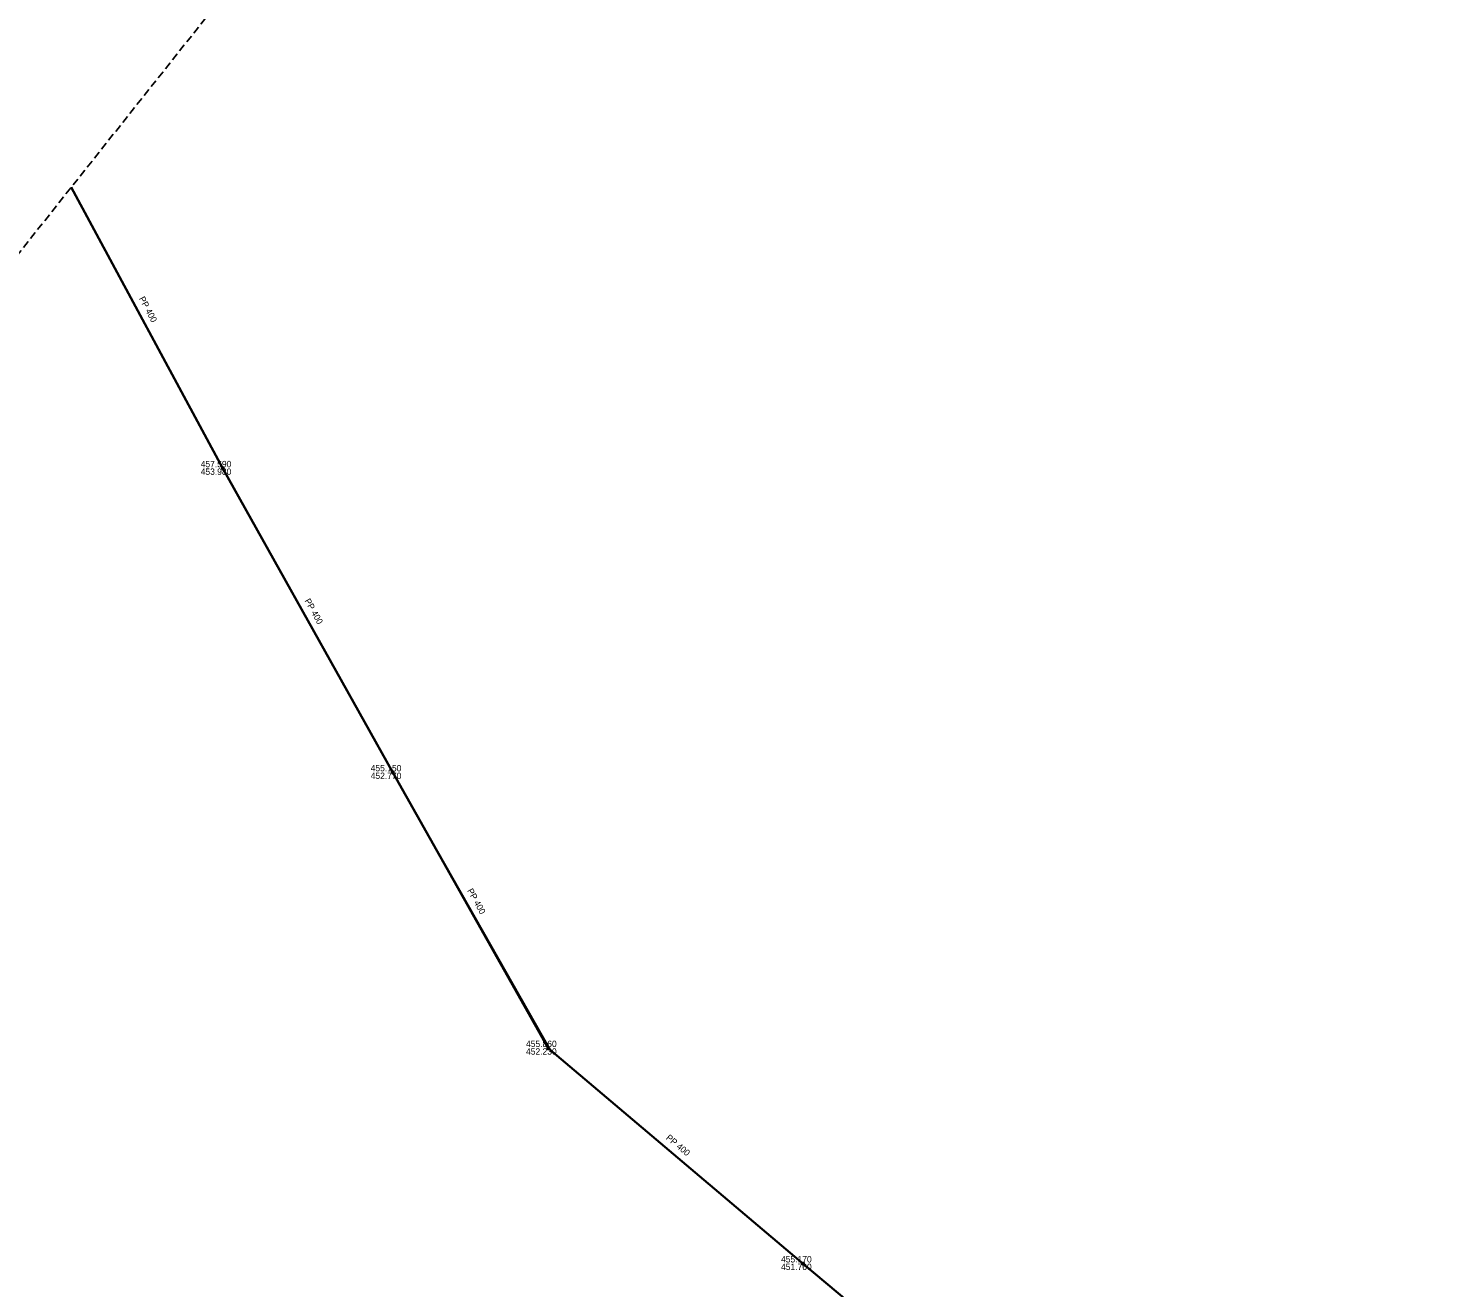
# Model space of a CAD drawing. Extents: x -873619 to -867639, y -1015082 to -1012326.
# Drawn here: x -873315.2 to -873071.1, y -1013648.8 to -1013430.2 of the extents above; entities that cross this region are included whole.
import ezdxf

# ---------------------------------------------------------------- set-up
doc = ezdxf.new("R2010")
doc.units = 0
doc.header["$LTSCALE"] = 0.44
doc.linetypes.add('MEDIUM_DASHED', pattern=[4.5, 3, -1.5])
for name, color, linetype, lineweight in [('1', 7, 'Continuous', 13), ('21', 7, 'Continuous', 35), ('3', 7, 'Continuous', 25), ('32', 7, 'Continuous', 13), ('62', 7, 'MEDIUM_DASHED', 25)]:
    doc.layers.add(name, color=color, linetype=linetype, lineweight=lineweight)

msp = doc.modelspace()

# ---------------------------------------------------------------- linework, layer by layer
at = {"layer": '21'}
for p, q in [((-873307.753, -1013457.817), (-873281.46, -1013506.61)), ((-873281.46, -1013506.61), (-873251.97, -1013559.37)), ((-873251.97, -1013559.37), (-873225.03, -1013607.21)), ((-873225.03, -1013607.21), (-873180.8, -1013644.59)), ((-873180.8, -1013644.59), (-873154.47, -1013666.63))]:
    msp.add_line(p, q, dxfattribs=at)
at = {"layer": '3'}
msp.add_lwpolyline([(-873209.421, -1014292.661), (-873208.998, -1014240.45), (-873211.448, -1014197.31), (-873215.58, -1014166.03), (-873205.44, -1014160.07), (-873195.92, -1014151.84), (-873190.998, -1014149.15), (-873189.02, -1014105.45), (-873184.64, -1014067), (-873178.998, -1014022.35), (-873173.208, -1014002.85), (-873150.578, -1013958.19), (-873123.56, -1013906.71), (-873116.49, -1013857.17), (-873096.298, -1013812.05), (-873076.908, -1013772.84), (-873099.08, -1013724.68), (-873112.568, -1013694.19), (-873154.458, -1013666.63), (-873180.788, -1013644.59), (-873224.641, -1013607.538), (-873251.958, -1013559.37), (-873281.448, -1013506.61), (-873307.717, -1013457.772)], dxfattribs=at)
at = {"layer": '32'}
for points in [[(-873281.218, -1013506.61), (-873281.225, -1013506.558), (-873281.242, -1013506.508), (-873281.271, -1013506.464), (-873281.308, -1013506.427), (-873281.353, -1013506.4), (-873281.402, -1013506.383), (-873281.456, -1013506.379), (-873281.507, -1013506.386), (-873281.556, -1013506.405), (-873281.6, -1013506.434), (-873281.636, -1013506.473), (-873281.662, -1013506.518), (-873281.678, -1013506.569), (-873281.681, -1013506.621), (-873281.673, -1013506.673), (-873281.652, -1013506.722), (-873281.622, -1013506.765), (-873281.583, -1013506.799), (-873281.537, -1013506.825), (-873281.485, -1013506.839), (-873281.433, -1013506.841), (-873281.382, -1013506.831), (-873281.333, -1013506.81), (-873281.291, -1013506.779), (-873281.257, -1013506.738), (-873281.233, -1013506.692), (-873281.22, -1013506.641)], [(-873281.249, -1013506.61), (-873281.255, -1013506.561), (-873281.272, -1013506.515), (-873281.299, -1013506.475), (-873281.337, -1013506.443), (-873281.38, -1013506.421), (-873281.429, -1013506.41), (-873281.478, -1013506.41), (-873281.524, -1013506.423), (-873281.568, -1013506.447), (-873281.603, -1013506.48), (-873281.63, -1013506.521), (-873281.647, -1013506.568), (-873281.651, -1013506.617), (-873281.644, -1013506.665), (-873281.625, -1013506.71), (-873281.595, -1013506.75), (-873281.556, -1013506.781), (-873281.512, -1013506.801), (-873281.465, -1013506.811), (-873281.416, -1013506.809), (-873281.369, -1013506.794), (-873281.326, -1013506.769), (-873281.291, -1013506.735), (-873281.266, -1013506.693), (-873281.252, -1013506.646)], [(-873281.279, -1013506.61), (-873281.284, -1013506.565), (-873281.301, -1013506.523), (-873281.33, -1013506.488), (-873281.365, -1013506.461), (-873281.407, -1013506.444), (-873281.453, -1013506.439), (-873281.497, -1013506.445), (-873281.539, -1013506.464), (-873281.573, -1013506.492), (-873281.6, -1013506.529), (-873281.617, -1013506.571), (-873281.62, -1013506.616), (-873281.614, -1013506.661), (-873281.595, -1013506.702), (-873281.566, -1013506.736), (-873281.529, -1013506.762), (-873281.485, -1013506.778), (-873281.441, -1013506.781), (-873281.396, -1013506.773), (-873281.355, -1013506.753), (-873281.321, -1013506.724), (-873281.296, -1013506.686), (-873281.282, -1013506.643)], [(-873281.309, -1013506.61), (-873281.313, -1013506.569), (-873281.331, -1013506.532), (-873281.358, -1013506.501), (-873281.394, -1013506.48), (-873281.434, -1013506.469), (-873281.475, -1013506.471), (-873281.514, -1013506.484), (-873281.548, -1013506.508), (-873281.573, -1013506.54), (-873281.588, -1013506.578), (-873281.59, -1013506.619), (-873281.583, -1013506.659), (-873281.563, -1013506.695), (-873281.534, -1013506.724), (-873281.497, -1013506.743), (-873281.456, -1013506.751), (-873281.416, -1013506.747), (-873281.377, -1013506.732), (-873281.345, -1013506.706), (-873281.323, -1013506.672), (-873281.309, -1013506.633)], [(-873281.338, -1013506.61), (-873281.343, -1013506.574), (-873281.362, -1013506.542), (-873281.387, -1013506.517), (-873281.421, -1013506.502), (-873281.458, -1013506.499), (-873281.492, -1013506.507), (-873281.524, -1013506.527), (-873281.546, -1013506.555), (-873281.559, -1013506.589), (-873281.559, -1013506.626), (-873281.549, -1013506.661), (-873281.527, -1013506.69), (-873281.497, -1013506.711), (-873281.463, -1013506.721), (-873281.426, -1013506.719), (-873281.392, -1013506.705), (-873281.365, -1013506.682), (-873281.345, -1013506.65), (-873281.338, -1013506.615)], [(-873281.369, -1013506.61), (-873281.374, -1013506.579), (-873281.391, -1013506.553), (-873281.416, -1013506.536), (-873281.446, -1013506.529), (-873281.478, -1013506.533), (-873281.505, -1013506.55), (-873281.522, -1013506.574), (-873281.531, -1013506.605), (-873281.527, -1013506.635), (-873281.512, -1013506.663), (-873281.487, -1013506.682), (-873281.458, -1013506.691), (-873281.426, -1013506.688), (-873281.399, -1013506.674), (-873281.379, -1013506.65), (-873281.369, -1013506.621)], [(-873281.399, -1013506.61), (-873281.404, -1013506.586), (-873281.421, -1013506.568), (-873281.443, -1013506.559), (-873281.468, -1013506.562), (-873281.489, -1013506.576), (-873281.5, -1013506.598), (-873281.5, -1013506.623), (-873281.487, -1013506.644), (-873281.468, -1013506.658), (-873281.443, -1013506.661), (-873281.419, -1013506.652), (-873281.404, -1013506.634)], [(-873281.429, -1013506.61), (-873281.434, -1013506.595), (-873281.448, -1013506.589), (-873281.463, -1013506.593), (-873281.47, -1013506.607), (-873281.467, -1013506.622), (-873281.453, -1013506.631), (-873281.438, -1013506.628), (-873281.429, -1013506.616)], [(-873251.728, -1013559.37), (-873251.735, -1013559.318), (-873251.752, -1013559.268), (-873251.781, -1013559.224), (-873251.818, -1013559.187), (-873251.863, -1013559.16), (-873251.913, -1013559.143), (-873251.966, -1013559.139), (-873252.017, -1013559.146), (-873252.066, -1013559.165), (-873252.11, -1013559.194), (-873252.146, -1013559.233), (-873252.172, -1013559.278), (-873252.188, -1013559.329), (-873252.191, -1013559.381), (-873252.183, -1013559.433), (-873252.163, -1013559.482), (-873252.132, -1013559.525), (-873252.093, -1013559.559), (-873252.047, -1013559.585), (-873251.995, -1013559.599), (-873251.943, -1013559.601), (-873251.892, -1013559.591), (-873251.843, -1013559.57), (-873251.801, -1013559.539), (-873251.767, -1013559.498), (-873251.743, -1013559.452), (-873251.73, -1013559.401)], [(-873251.759, -1013559.37), (-873251.765, -1013559.321), (-873251.782, -1013559.275), (-873251.809, -1013559.235), (-873251.847, -1013559.203), (-873251.891, -1013559.181), (-873251.939, -1013559.17), (-873251.988, -1013559.17), (-873252.034, -1013559.183), (-873252.078, -1013559.207), (-873252.114, -1013559.24), (-873252.141, -1013559.281), (-873252.157, -1013559.328), (-873252.161, -1013559.377), (-873252.154, -1013559.425), (-873252.135, -1013559.47), (-873252.105, -1013559.51), (-873252.066, -1013559.541), (-873252.022, -1013559.561), (-873251.975, -1013559.571), (-873251.926, -1013559.569), (-873251.879, -1013559.554), (-873251.836, -1013559.529), (-873251.801, -1013559.495), (-873251.776, -1013559.453), (-873251.762, -1013559.406)], [(-873251.789, -1013559.37), (-873251.794, -1013559.325), (-873251.811, -1013559.283), (-873251.84, -1013559.248), (-873251.875, -1013559.221), (-873251.918, -1013559.204), (-873251.963, -1013559.199), (-873252.007, -1013559.205), (-873252.049, -1013559.224), (-873252.083, -1013559.252), (-873252.11, -1013559.289), (-873252.127, -1013559.331), (-873252.13, -1013559.376), (-873252.124, -1013559.421), (-873252.105, -1013559.462), (-873252.076, -1013559.496), (-873252.039, -1013559.522), (-873251.995, -1013559.538), (-873251.951, -1013559.541), (-873251.906, -1013559.533), (-873251.865, -1013559.513), (-873251.831, -1013559.484), (-873251.806, -1013559.446), (-873251.792, -1013559.403)], [(-873251.819, -1013559.37), (-873251.823, -1013559.329), (-873251.842, -1013559.292), (-873251.869, -1013559.261), (-873251.904, -1013559.24), (-873251.944, -1013559.229), (-873251.985, -1013559.231), (-873252.024, -1013559.244), (-873252.058, -1013559.268), (-873252.083, -1013559.3), (-873252.098, -1013559.338), (-873252.1, -1013559.379), (-873252.093, -1013559.419), (-873252.073, -1013559.455), (-873252.044, -1013559.484), (-873252.007, -1013559.503), (-873251.967, -1013559.511), (-873251.926, -1013559.507), (-873251.887, -1013559.492), (-873251.855, -1013559.466), (-873251.833, -1013559.432), (-873251.82, -1013559.393)], [(-873251.848, -1013559.37), (-873251.853, -1013559.334), (-873251.872, -1013559.302), (-873251.897, -1013559.277), (-873251.931, -1013559.262), (-873251.968, -1013559.259), (-873252.002, -1013559.267), (-873252.034, -1013559.287), (-873252.056, -1013559.315), (-873252.07, -1013559.349), (-873252.07, -1013559.386), (-873252.059, -1013559.421), (-873252.038, -1013559.45), (-873252.007, -1013559.471), (-873251.973, -1013559.481), (-873251.936, -1013559.479), (-873251.902, -1013559.465), (-873251.875, -1013559.442), (-873251.855, -1013559.41), (-873251.848, -1013559.375)], [(-873251.879, -1013559.37), (-873251.884, -1013559.339), (-873251.901, -1013559.313), (-873251.926, -1013559.296), (-873251.956, -1013559.289), (-873251.988, -1013559.293), (-873252.015, -1013559.31), (-873252.032, -1013559.334), (-873252.041, -1013559.365), (-873252.037, -1013559.395), (-873252.022, -1013559.423), (-873251.997, -1013559.442), (-873251.968, -1013559.451), (-873251.936, -1013559.448), (-873251.909, -1013559.434), (-873251.889, -1013559.41), (-873251.879, -1013559.381)], [(-873251.909, -1013559.37), (-873251.914, -1013559.346), (-873251.931, -1013559.328), (-873251.953, -1013559.319), (-873251.978, -1013559.322), (-873251.999, -1013559.336), (-873252.01, -1013559.358), (-873252.01, -1013559.383), (-873251.997, -1013559.404), (-873251.978, -1013559.418), (-873251.953, -1013559.421), (-873251.929, -1013559.412), (-873251.914, -1013559.394)], [(-873251.939, -1013559.37), (-873251.944, -1013559.355), (-873251.958, -1013559.349), (-873251.973, -1013559.353), (-873251.98, -1013559.367), (-873251.977, -1013559.382), (-873251.963, -1013559.391), (-873251.948, -1013559.388), (-873251.939, -1013559.376)], [(-873224.789, -1013607.21), (-873224.795, -1013607.158), (-873224.812, -1013607.108), (-873224.841, -1013607.064), (-873224.878, -1013607.027), (-873224.923, -1013607), (-873224.973, -1013606.983), (-873225.026, -1013606.979), (-873225.078, -1013606.986), (-873225.127, -1013607.005), (-873225.17, -1013607.034), (-873225.206, -1013607.073), (-873225.232, -1013607.118), (-873225.248, -1013607.169), (-873225.251, -1013607.221), (-873225.243, -1013607.273), (-873225.223, -1013607.322), (-873225.192, -1013607.365), (-873225.153, -1013607.399), (-873225.107, -1013607.425), (-873225.056, -1013607.439), (-873225.003, -1013607.441), (-873224.952, -1013607.431), (-873224.904, -1013607.41), (-873224.861, -1013607.379), (-873224.827, -1013607.338), (-873224.803, -1013607.292), (-873224.791, -1013607.241)], [(-873224.819, -1013607.21), (-873224.825, -1013607.161), (-873224.842, -1013607.115), (-873224.87, -1013607.075), (-873224.907, -1013607.043), (-873224.951, -1013607.021), (-873224.999, -1013607.01), (-873225.048, -1013607.01), (-873225.095, -1013607.023), (-873225.138, -1013607.047), (-873225.174, -1013607.08), (-873225.201, -1013607.121), (-873225.217, -1013607.168), (-873225.221, -1013607.217), (-873225.214, -1013607.265), (-873225.195, -1013607.31), (-873225.165, -1013607.35), (-873225.127, -1013607.381), (-873225.083, -1013607.401), (-873225.035, -1013607.411), (-873224.986, -1013607.409), (-873224.939, -1013607.394), (-873224.896, -1013607.369), (-873224.862, -1013607.335), (-873224.836, -1013607.293), (-873224.822, -1013607.246)], [(-873224.849, -1013607.21), (-873224.855, -1013607.165), (-873224.872, -1013607.123), (-873224.9, -1013607.088), (-873224.936, -1013607.061), (-873224.978, -1013607.044), (-873225.023, -1013607.039), (-873225.068, -1013607.045), (-873225.109, -1013607.064), (-873225.144, -1013607.092), (-873225.171, -1013607.129), (-873225.187, -1013607.171), (-873225.191, -1013607.216), (-873225.184, -1013607.261), (-873225.165, -1013607.302), (-873225.136, -1013607.336), (-873225.099, -1013607.362), (-873225.056, -1013607.378), (-873225.011, -1013607.381), (-873224.966, -1013607.373), (-873224.926, -1013607.353), (-873224.892, -1013607.324), (-873224.866, -1013607.286), (-873224.852, -1013607.243)], [(-873224.879, -1013607.21), (-873224.884, -1013607.169), (-873224.902, -1013607.132), (-873224.929, -1013607.101), (-873224.964, -1013607.08), (-873225.004, -1013607.069), (-873225.045, -1013607.071), (-873225.084, -1013607.084), (-873225.118, -1013607.108), (-873225.143, -1013607.14), (-873225.158, -1013607.178), (-873225.161, -1013607.219), (-873225.153, -1013607.259), (-873225.133, -1013607.295), (-873225.104, -1013607.324), (-873225.067, -1013607.343), (-873225.027, -1013607.351), (-873224.986, -1013607.347), (-873224.948, -1013607.332), (-873224.916, -1013607.306), (-873224.893, -1013607.272), (-873224.88, -1013607.233)], [(-873224.909, -1013607.21), (-873224.914, -1013607.174), (-873224.932, -1013607.142), (-873224.958, -1013607.117), (-873224.992, -1013607.102), (-873225.028, -1013607.099), (-873225.063, -1013607.107), (-873225.094, -1013607.127), (-873225.117, -1013607.155), (-873225.13, -1013607.189), (-873225.13, -1013607.226), (-873225.119, -1013607.261), (-873225.098, -1013607.29), (-873225.068, -1013607.311), (-873225.033, -1013607.321), (-873224.996, -1013607.319), (-873224.962, -1013607.305), (-873224.935, -1013607.282), (-873224.916, -1013607.25), (-873224.909, -1013607.215)], [(-873224.939, -1013607.21), (-873224.944, -1013607.179), (-873224.961, -1013607.153), (-873224.987, -1013607.136), (-873225.017, -1013607.129), (-873225.048, -1013607.133), (-873225.075, -1013607.15), (-873225.093, -1013607.174), (-873225.101, -1013607.205), (-873225.097, -1013607.235), (-873225.082, -1013607.263), (-873225.058, -1013607.282), (-873225.028, -1013607.291), (-873224.997, -1013607.288), (-873224.969, -1013607.274), (-873224.949, -1013607.25), (-873224.939, -1013607.221)], [(-873224.969, -1013607.21), (-873224.974, -1013607.186), (-873224.991, -1013607.168), (-873225.014, -1013607.159), (-873225.038, -1013607.162), (-873225.059, -1013607.176), (-873225.07, -1013607.198), (-873225.07, -1013607.223), (-873225.058, -1013607.244), (-873225.038, -1013607.258), (-873225.013, -1013607.261), (-873224.99, -1013607.252), (-873224.974, -1013607.234)], [(-873224.999, -1013607.21), (-873225.004, -1013607.195), (-873225.019, -1013607.189), (-873225.034, -1013607.193), (-873225.041, -1013607.207), (-873225.037, -1013607.222), (-873225.024, -1013607.231), (-873225.009, -1013607.228), (-873224.999, -1013607.216)], [(-873180.559, -1013644.59), (-873180.565, -1013644.538), (-873180.582, -1013644.488), (-873180.611, -1013644.444), (-873180.648, -1013644.407), (-873180.693, -1013644.38), (-873180.743, -1013644.363), (-873180.796, -1013644.359), (-873180.848, -1013644.366), (-873180.897, -1013644.385), (-873180.94, -1013644.414), (-873180.976, -1013644.453), (-873181.002, -1013644.498), (-873181.018, -1013644.549), (-873181.021, -1013644.601), (-873181.013, -1013644.653), (-873180.993, -1013644.702), (-873180.962, -1013644.745), (-873180.923, -1013644.779), (-873180.877, -1013644.805), (-873180.826, -1013644.819), (-873180.773, -1013644.821), (-873180.722, -1013644.811), (-873180.674, -1013644.79), (-873180.631, -1013644.759), (-873180.597, -1013644.718), (-873180.573, -1013644.672), (-873180.561, -1013644.621)], [(-873180.589, -1013644.59), (-873180.595, -1013644.541), (-873180.612, -1013644.495), (-873180.64, -1013644.455), (-873180.677, -1013644.423), (-873180.721, -1013644.401), (-873180.769, -1013644.39), (-873180.818, -1013644.39), (-873180.865, -1013644.403), (-873180.908, -1013644.427), (-873180.944, -1013644.46), (-873180.971, -1013644.501), (-873180.987, -1013644.548), (-873180.991, -1013644.597), (-873180.984, -1013644.645), (-873180.965, -1013644.69), (-873180.935, -1013644.73), (-873180.897, -1013644.761), (-873180.853, -1013644.781), (-873180.805, -1013644.791), (-873180.756, -1013644.789), (-873180.709, -1013644.774), (-873180.666, -1013644.749), (-873180.632, -1013644.715), (-873180.606, -1013644.673), (-873180.592, -1013644.626)], [(-873180.619, -1013644.59), (-873180.625, -1013644.545), (-873180.642, -1013644.503), (-873180.67, -1013644.468), (-873180.706, -1013644.441), (-873180.748, -1013644.424), (-873180.793, -1013644.419), (-873180.838, -1013644.425), (-873180.879, -1013644.444), (-873180.914, -1013644.472), (-873180.941, -1013644.509), (-873180.957, -1013644.551), (-873180.961, -1013644.596), (-873180.954, -1013644.641), (-873180.935, -1013644.682), (-873180.906, -1013644.716), (-873180.869, -1013644.742), (-873180.826, -1013644.758), (-873180.781, -1013644.761), (-873180.736, -1013644.753), (-873180.696, -1013644.733), (-873180.662, -1013644.704), (-873180.636, -1013644.666), (-873180.622, -1013644.623)], [(-873180.649, -1013644.59), (-873180.654, -1013644.549), (-873180.672, -1013644.512), (-873180.699, -1013644.481), (-873180.734, -1013644.46), (-873180.774, -1013644.449), (-873180.815, -1013644.451), (-873180.854, -1013644.464), (-873180.888, -1013644.488), (-873180.913, -1013644.52), (-873180.928, -1013644.558), (-873180.931, -1013644.599), (-873180.923, -1013644.639), (-873180.903, -1013644.675), (-873180.874, -1013644.704), (-873180.837, -1013644.723), (-873180.797, -1013644.731), (-873180.756, -1013644.727), (-873180.718, -1013644.712), (-873180.686, -1013644.686), (-873180.663, -1013644.652), (-873180.65, -1013644.613)], [(-873180.679, -1013644.59), (-873180.684, -1013644.554), (-873180.702, -1013644.522), (-873180.728, -1013644.497), (-873180.762, -1013644.482), (-873180.798, -1013644.479), (-873180.833, -1013644.487), (-873180.864, -1013644.507), (-873180.887, -1013644.535), (-873180.9, -1013644.569), (-873180.9, -1013644.606), (-873180.889, -1013644.641), (-873180.868, -1013644.67), (-873180.838, -1013644.691), (-873180.803, -1013644.701), (-873180.766, -1013644.699), (-873180.732, -1013644.685), (-873180.705, -1013644.662), (-873180.686, -1013644.63), (-873180.679, -1013644.595)], [(-873180.709, -1013644.59), (-873180.714, -1013644.559), (-873180.731, -1013644.533), (-873180.757, -1013644.516), (-873180.787, -1013644.509), (-873180.818, -1013644.513), (-873180.845, -1013644.53), (-873180.863, -1013644.554), (-873180.871, -1013644.585), (-873180.867, -1013644.615), (-873180.852, -1013644.643), (-873180.828, -1013644.662), (-873180.798, -1013644.671), (-873180.767, -1013644.668), (-873180.739, -1013644.654), (-873180.719, -1013644.63), (-873180.709, -1013644.601)], [(-873180.739, -1013644.59), (-873180.744, -1013644.566), (-873180.761, -1013644.548), (-873180.784, -1013644.539), (-873180.808, -1013644.542), (-873180.829, -1013644.556), (-873180.84, -1013644.578), (-873180.84, -1013644.603), (-873180.828, -1013644.624), (-873180.808, -1013644.638), (-873180.783, -1013644.641), (-873180.76, -1013644.632), (-873180.744, -1013644.614)], [(-873180.769, -1013644.59), (-873180.774, -1013644.575), (-873180.789, -1013644.569), (-873180.804, -1013644.573), (-873180.811, -1013644.587), (-873180.807, -1013644.602), (-873180.794, -1013644.611), (-873180.779, -1013644.608), (-873180.769, -1013644.596)]]:
    msp.add_lwpolyline(points, close=True, dxfattribs=at)
at = {"layer": '62'}
msp.add_lwpolyline([(-873556.163, -1013770.63), (-872990.942, -1013058.87), (-872369.897, -1012591.341), (-871448.796, -1012465.737), (-870583.52, -1012702.99), (-868999.506, -1012326.176), (-868524.999, -1012528.539), (-868252.856, -1012577.385), (-867687.635, -1012737.88), (-867638.789, -1013044.914), (-867827.196, -1013184.475), (-868176.097, -1013763.652), (-868434.285, -1014335.85), (-868650.604, -1014635.906), (-869550.77, -1014963.874), (-870206.706, -1015082.5), (-871092.916, -1015026.676), (-871923.303, -1014566.126), (-872607.15, -1014370.741), (-872865.338, -1014447.499), (-873284.02, -1014259.092), (-873402.646, -1014252.114), (-873618.965, -1014280.026)], close=True, dxfattribs=at)

# ---------------------------------------------------------------- texts
at = {"layer": '1'}
for rotation, p in [(298, (-873296.042, -1013477.123)), (299, (-873267.321, -1013529.547)), (299, (-873239.116, -1013579.849)), (320, (-873204.692, -1013622.89))]:
    msp.add_text('PP 400', height=1.1, rotation=rotation, dxfattribs=at).set_placement(p)
for s, p in [('457.590 ', (-873285.3, -1013506.39)), ('453.980 ', (-873285.3, -1013507.71)), ('455.150 ', (-873255.81, -1013559.15)), ('452.770 ', (-873255.81, -1013560.47)), ('455.860 ', (-873228.87, -1013606.99)), ('452.230 ', (-873228.87, -1013608.31)), ('455.170 ', (-873184.64, -1013644.37)), ('451.760 ', (-873184.64, -1013645.69))]:
    msp.add_text(s, height=1.1, dxfattribs=at).set_placement(p)

doc.saveas('drawing.dxf')
